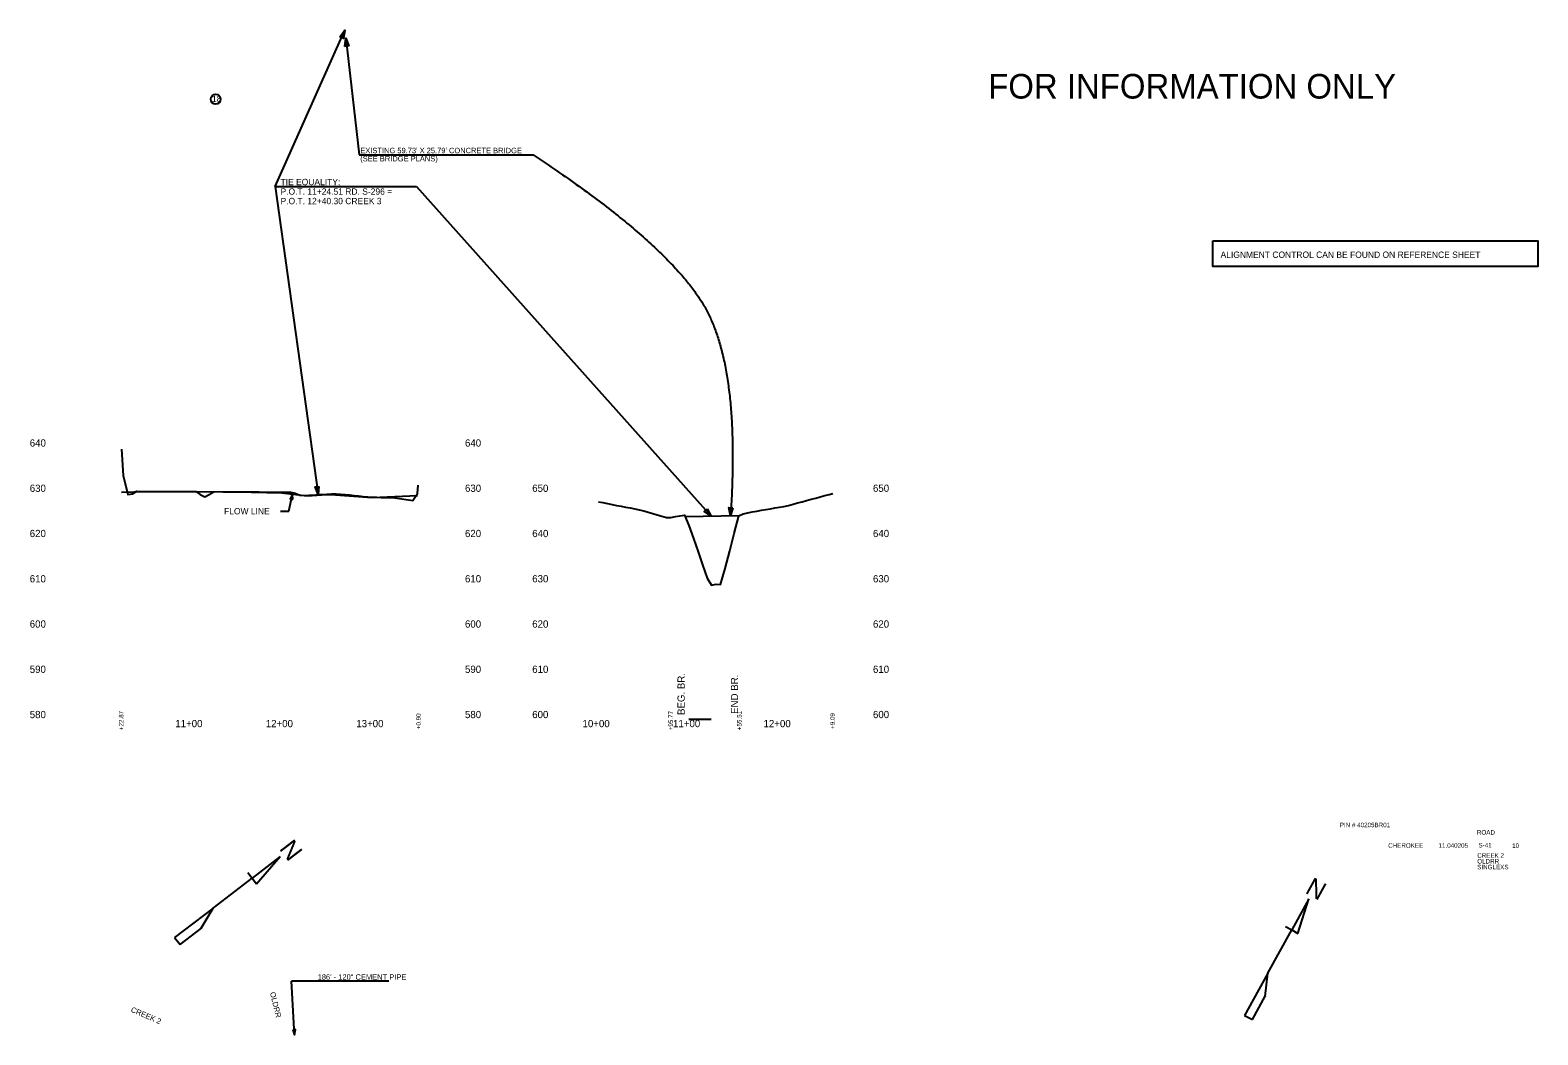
# Model space of a CAD drawing. Extents: x 16382402 to 16388022, y 46194326 to 46202918.
# Drawn here: x 16384273 to 16385939, y 46199872 to 46200982 of the extents above; entities that cross this region are included whole.
import ezdxf

# ---------------------------------------------------------------- set-up
doc = ezdxf.new("R2010")
doc.units = 0
for name, color, linetype in [('RD_DDB_ElevTX', 7, 'Continuous'), ('RD_DDB_Profile_EX', 7, 'Continuous'), ('RD_DDB_Profile_Lbl', 7, 'Continuous'), ('RD_DDB_StaTX', 7, 'Continuous'), ('RD_EX_Bridge', 7, 'Continuous'), ('RD_EX_DV_Prop', 7, 'Continuous'), ('RD_EX_Misc', 7, 'Continuous'), ('RD_HC_Data', 7, 'Continuous'), ('RD_PD_Final_TX', 7, 'Continuous'), ('RD_SHT_SubGrid', 7, 'Continuous'), ('RD_Sketch1', 7, 'Continuous'), ('RD_TX_Drainage', 7, 'Continuous'), ('RD_TX_Misc1', 7, 'Continuous'), ('RD_TX_RoadID', 7, 'Continuous')]:
    doc.layers.add(name, color=color, linetype=linetype)

msp = doc.modelspace()

# ---------------------------------------------------------------- linework, layer by layer
at = {"layer": 'RD_DDB_Profile_EX'}
for points in [[(16384374.2, 46200519), (16384376.4, 46200489.9), (16384381.4, 46200468.8), (16384386.4, 46200469.7), (16384391.4, 46200472.4), (16384396.4, 46200472.3), (16384401.4, 46200472.3), (16384406.4, 46200472.3), (16384411.4, 46200472.3), (16384416.4, 46200472.3), (16384421.4, 46200472.3), (16384426.4, 46200472.2), (16384431.4, 46200472.2), (16384436.4, 46200472.2), (16384441.4, 46200472.2), (16384446.4, 46200472.2), (16384451.4, 46200472.2), (16384456.4, 46200472.2), (16384461.4, 46200468.9), (16384466.4, 46200466.4), (16384471.4, 46200469), (16384476.4, 46200471.7), (16384481.4, 46200472.1), (16384486.4, 46200472), (16384491.4, 46200471.9), (16384496.4, 46200471.9), (16384501.4, 46200471.9), (16384506.4, 46200471.9), (16384511.4, 46200471.8), (16384516.4, 46200471.7), (16384521.4, 46200471.7), (16384526.4, 46200471.7), (16384531.4, 46200471.6), (16384536.4, 46200471.6), (16384541.4, 46200471.5), (16384546.4, 46200471.5), (16384551.4, 46200471.5), (16384556.4, 46200471.4), (16384561.4, 46200471.3), (16384566.4, 46200470.5), (16384571.4, 46200468.2), (16384576.4, 46200467.7), (16384581.4, 46200468), (16384586.4, 46200468.3), (16384591.4, 46200468.7), (16384596.4, 46200469), (16384601.4, 46200469.3), (16384606.4, 46200469.6), (16384611.4, 46200469.6), (16384616.4, 46200469.3), (16384621.4, 46200468.8), (16384626.4, 46200468.4), (16384631.4, 46200467.9), (16384636.4, 46200467.4), (16384641.4, 46200466.8), (16384646.4, 46200466.2), (16384651.4, 46200465.9), (16384656.4, 46200465.8), (16384661.4, 46200465.7), (16384666.4, 46200465.7), (16384671.4, 46200465.6), (16384676.4, 46200465.1), (16384681.4, 46200464.4), (16384686.4, 46200463.7), (16384691.4, 46200463), (16384696.4, 46200462.3), (16384701.4, 46200470.1), (16384702.3, 46200479.3)], [(16384374.2, 46200471.6), (16384401.4, 46200472.1), (16384451.4, 46200472.1), (16384501.4, 46200471.7), (16384551.4, 46200470.8), (16384579.6, 46200467.4), (16384601.4, 46200468.8), (16384605.5, 46200468.9), (16384651.4, 46200465.4), (16384701.4, 46200467.6)], [(16384901.4, 46200460.9), (16384906.4, 46200459.9), (16384911.4, 46200458.9), (16384916.4, 46200457.9), (16384921.4, 46200456.9), (16384926.4, 46200456), (16384931.4, 46200455), (16384936.4, 46200454), (16384941.4, 46200453), (16384946.4, 46200452), (16384951.4, 46200450.7), (16384956.4, 46200449.3), (16384961.4, 46200447.9), (16384966.4, 46200446.5), (16384971.4, 46200445), (16384976.4, 46200443.6), (16384981.4, 46200443.6), (16384986.4, 46200444.5), (16384991.4, 46200445.3), (16384996.4, 46200446.1), (16385001.4, 46200434.6), (16385006.4, 46200420.1), (16385011.4, 46200405.5), (16385016.4, 46200391), (16385021.4, 46200376.5), (16385026.4, 46200368.8), (16385031.4, 46200370), (16385036.4, 46200369.6), (16385041.4, 46200387.1), (16385046.4, 46200406.5), (16385051.4, 46200425.9), (16385056.4, 46200445.2), (16385061.4, 46200447.7), (16385066.4, 46200448.8), (16385071.4, 46200449.7), (16385076.4, 46200450.6), (16385081.4, 46200451.4), (16385086.4, 46200452.3), (16385091.4, 46200453.2), (16385096.4, 46200454), (16385101.4, 46200454.9), (16385106.4, 46200455.8), (16385111.4, 46200456.9), (16385116.4, 46200458.2), (16385121.4, 46200459.6), (16385126.4, 46200460.9), (16385131.4, 46200462.2), (16385136.4, 46200463.6), (16385141.4, 46200464.9), (16385146.4, 46200466.2), (16385151.4, 46200467.6), (16385156.4, 46200468.9), (16385160.4, 46200470)]]:
    msp.add_lwpolyline(points, dxfattribs=at)
at = {"layer": 'RD_EX_Bridge'}
for p, q in [((16384622.2, 46200973.2), (16384637, 46200844.1)), ((16384637, 46200844.1), (16384829.2, 46200844.1))]:
    msp.add_line(p, q, dxfattribs=at)
msp.add_open_spline([(16384829.2, 46200844.1), (16384979.7, 46200745), (16385058.2, 46200606.5), (16385047.3, 46200445.3)], degree=2, dxfattribs=at)
at = {"layer": 'RD_EX_DV_Prop'}
msp.add_circle((16384478.4, 46200905.6), 5.49, dxfattribs=at)
at = {"layer": 'RD_EX_Misc'}
for p, q in [((16384549.8, 46200069), (16384518.7, 46200045.1)), ((16384523.5, 46200038.9), (16384549.8, 46200069)), ((16384549.8, 46200069), (16384549.8, 46200069)), ((16384513.9, 46200051.3), (16384518.7, 46200045.1)), ((16384475.5, 46200012), (16384518.7, 46200045.1)), ((16384518.7, 46200045.1), (16384523.5, 46200038.9)), ((16384523.5, 46200038.9), (16384523.8, 46200039.2)), ((16385686.3, 46200022.2), (16385667.4, 46199987.8)), ((16385674.3, 46199984), (16385686.3, 46200022.2)), ((16385686.3, 46200022.2), (16385686.3, 46200022.2)), ((16384475.5, 46200012), (16384433.1, 46199979.5)), ((16384462.4, 46199989.6), (16384475.5, 46200012)), ((16384439.1, 46199971.8), (16384462.6, 46199989.8)), ((16384462.6, 46199989.8), (16384462.4, 46199989.6)), ((16385641.1, 46199940.2), (16385667.4, 46199987.8)), ((16385660.5, 46199991.6), (16385667.4, 46199987.8)), ((16385667.4, 46199987.8), (16385674.3, 46199984)), ((16385674.3, 46199984), (16385674.5, 46199984.5)), ((16384433.1, 46199979.5), (16384439.1, 46199971.8)), ((16385641.1, 46199940.2), (16385615.3, 46199893.4)), ((16385638.1, 46199914.4), (16385641.1, 46199940.2)), ((16385623.9, 46199888.7), (16385638.2, 46199914.7)), ((16385638.2, 46199914.7), (16385638.1, 46199914.4)), ((16385615.3, 46199893.4), (16385623.9, 46199888.7))]:
    msp.add_line(p, q, dxfattribs=at)
at = {"layer": 'RD_HC_Data'}
for p, q in [((16384544.1, 46200809.2), (16384621.3, 46200981.9)), ((16384544.1, 46200809.2), (16384700.4, 46200809.2)), ((16384544.1, 46200809.2), (16384591.7, 46200468.7)), ((16384700.4, 46200809.2), (16385025.9, 46200444.9))]:
    msp.add_line(p, q, dxfattribs=at)
at = {"layer": 'RD_SHT_SubGrid'}
msp.add_line((16385001.4, 46200220.8), (16385025.9, 46200220.8), dxfattribs=at)
at = {"layer": 'RD_Sketch1'}
msp.add_lwpolyline([(16385580.2, 46200749.2), (16385939.4, 46200749.2), (16385939.4, 46200720.8), (16385580.2, 46200720.8)], close=True, dxfattribs=at)
at = {"layer": 'RD_TX_Drainage'}
for p in [(16384669.9, 46199931.3), (16384565.5, 46199871.9)]:
    msp.add_line(p, (16384562.3, 46199931.3), dxfattribs=at)
for points in [[(16384615.6, 46200974.6), (16384621.3, 46200981.9), (16384619.7, 46200972.7)], [(16384621, 46200964), (16384622.2, 46200973.2), (16384625.5, 46200964.5)], [(16384563.7, 46200463.4), (16384563.4, 46200469.3), (16384560.6, 46200464)], [(16384592.6, 46200477.9), (16384591.7, 46200468.7), (16384588.2, 46200477.3)], [(16385021.5, 46200453.1), (16385025.9, 46200444.9), (16385018.2, 46200450.1)], [(16385050, 46200454.2), (16385047.3, 46200445.3), (16385045.5, 46200454.4)], [(16384563.6, 46199877.6), (16384565.5, 46199871.9), (16384566.7, 46199877.8)]]:
    msp.add_lwpolyline(points, close=True, dxfattribs=at)
at = {"layer": 'RD_TX_Misc1'}
for p, q in [((16384559.3, 46200450.3), (16384563.4, 46200469.3)), ((16384549.9, 46200450.3), (16384559.3, 46200450.3)), ((16384997.1, 46200444.4), (16385056.9, 46200445.5))]:
    msp.add_line(p, q, dxfattribs=at)

# ---------------------------------------------------------------- texts
at = {"layer": 'RD_DDB_ElevTX'}
for s, p in [('640', (16384273, 46200521.8)), ('640', (16384753.9, 46200521.8)), ('630', (16384273, 46200471.8)), ('630', (16384753.9, 46200471.8)), ('650', (16384828.2, 46200471.8)), ('650', (16385204.7, 46200471.8)), ('620', (16384273, 46200421.8)), ('620', (16384753.9, 46200421.8)), ('640', (16384828.2, 46200421.8)), ('640', (16385204.7, 46200421.8)), ('610', (16384273, 46200371.8)), ('610', (16384753.9, 46200371.8)), ('630', (16384828.2, 46200371.8)), ('630', (16385204.7, 46200371.8)), ('600', (16384273, 46200321.8)), ('600', (16384753.9, 46200321.8)), ('620', (16384828.2, 46200321.8)), ('620', (16385204.7, 46200321.8)), ('590', (16384273, 46200271.8)), ('590', (16384753.9, 46200271.8)), ('610', (16384828.2, 46200271.8)), ('610', (16385204.7, 46200271.8)), ('580', (16384273, 46200221.8)), ('580', (16384753.9, 46200221.8)), ('600', (16384828.2, 46200221.8)), ('600', (16385204.7, 46200221.8))]:
    msp.add_text(s, height=8, dxfattribs=at).set_placement(p)
at = {"layer": 'RD_DDB_Profile_Lbl'}
msp.add_text('FLOW LINE', height=7, dxfattribs=at).set_placement((16384487.7, 46200446.9))
at = {"layer": 'RD_DDB_StaTX'}
for s, height, p in [('BEG. BR.', 8, (16384996.7, 46200225.3)), ('END BR.', 8, (16385055.7, 46200226.5)), ('+22.87', 5, (16384376.5, 46200208.5)), ('+0.90', 5, (16384705, 46200209.6)), ('+95.77', 5, (16384983.7, 46200208.4)), ('+55.51', 5, (16385059.5, 46200208.5)), ('+9.09', 5, (16385162.5, 46200209.9))]:
    msp.add_text(s, height=height, rotation=90, dxfattribs=at).set_placement(p)
for s, p in [('11+00', (16384433.8, 46200211.8)), ('12+00', (16384533.8, 46200211.8)), ('13+00', (16384633.8, 46200211.8)), ('10+00', (16384883.8, 46200211.8)), ('11+00', (16384983.8, 46200211.8)), ('12+00', (16385083.8, 46200211.8))]:
    msp.add_text(s, height=8, dxfattribs=at).set_placement(p)
at = {"layer": 'RD_EX_Bridge'}
for s, p in [("EXISTING 59.73' X 25.79' CONCRETE BRIDGE", (16384638.2, 46200845.9)), ('(SEE BRIDGE PLANS)', (16384638.2, 46200836.9))]:
    msp.add_text(s, height=6, dxfattribs=at).set_placement(p)
at = {"layer": 'RD_EX_DV_Prop'}
msp.add_text('18', height=7, dxfattribs=at).set_placement((16384474.4, 46200902.5))
at = {"layer": 'RD_EX_Misc'}
for s, p in [('PIN # 40205BR01', (16385720.5, 46200101.3)), ('ROAD', (16385872, 46200093.1)), ('CHEROKEE', (16385774, 46200078.6)), ('11.040205 ', (16385829.6, 46200078.6)), ('S-41', (16385873.8, 46200078.9)), ('10', (16385911, 46200078.4)), ('CREEK 2', (16385872.4, 46200067.5)), ('OLDRR', (16385872.4, 46200061.2)), ('SINGLEXS', (16385872.4, 46200054.8))]:
    msp.add_text(s, height=5, dxfattribs=at).set_placement(p)
for rotation, p in [(307.461, (16384548, 46200077.5)), (331.127, (16385681.2, 46200029.2))]:
    msp.add_text('N', height=20, rotation=rotation, dxfattribs=at).set_placement(p)
at = {"layer": 'RD_HC_Data'}
for s, p in [('TIE EQUALITY:', (16384550.1, 46200810.6)), ('P.O.T. 11+24.51 RD. S-296 =', (16384550.1, 46200800.1)), ('P.O.T. 12+40.30 CREEK 3', (16384550.1, 46200789.6))]:
    msp.add_text(s, height=7, dxfattribs=at).set_placement(p)
at = {"layer": 'RD_PD_Final_TX'}
msp.add_text('FOR INFORMATION ONLY', height=27.205, dxfattribs=at).set_placement((16385332, 46200906.3))
at = {"layer": 'RD_Sketch1'}
msp.add_text('ALIGNMENT CONTROL CAN BE FOUND ON REFERENCE SHEET', height=7, dxfattribs=at).set_placement((16385588.8, 46200730.3))
at = {"layer": 'RD_TX_Drainage'}
msp.add_text('     186\' - 120" CEMENT PIPE', height=6, dxfattribs=at).set_placement((16384579.6, 46199932.8))
at = {"layer": 'RD_TX_RoadID'}
for s, rotation, p in [('OLDRR', 283.5074, (16384538.4, 46199918.5)), ('CREEK 2', 336.6279, (16384384.1, 46199897.6))]:
    msp.add_text(s, height=6, rotation=rotation, dxfattribs=at).set_placement(p)

doc.saveas('drawing.dxf')
